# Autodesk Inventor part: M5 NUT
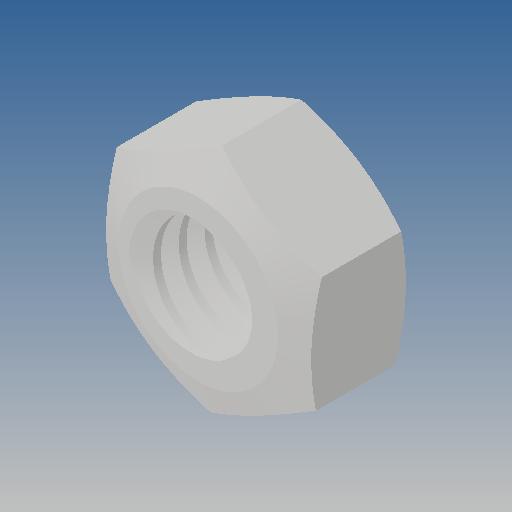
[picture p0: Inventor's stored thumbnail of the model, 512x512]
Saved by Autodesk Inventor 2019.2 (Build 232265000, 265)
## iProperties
Created: 2012-09
Part Number: M5 NUT
Material: Ogólny
Document SubType Name: Modeling
Designer: CADENGINEERING4
Density: 1 g/cm^3
Appearance: Domyślna
Author: CADENGINEERING4
Revision Number: ÈÎºÎ
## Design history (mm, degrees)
feature "ÇÐ³ý-É¨Ãè2"
node "Bryła1"
